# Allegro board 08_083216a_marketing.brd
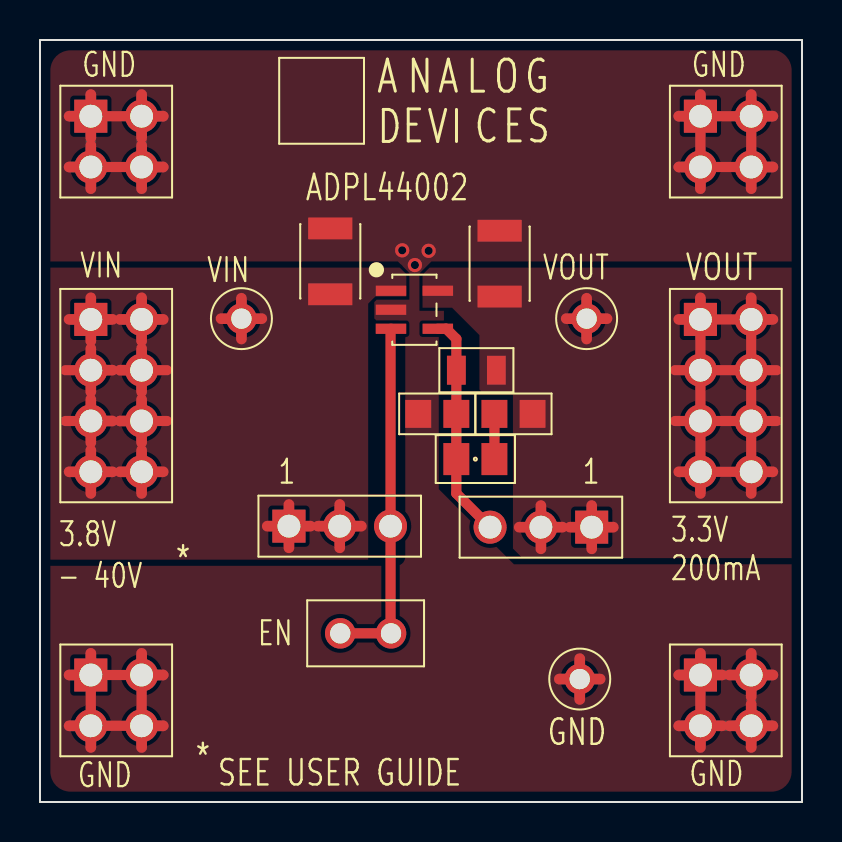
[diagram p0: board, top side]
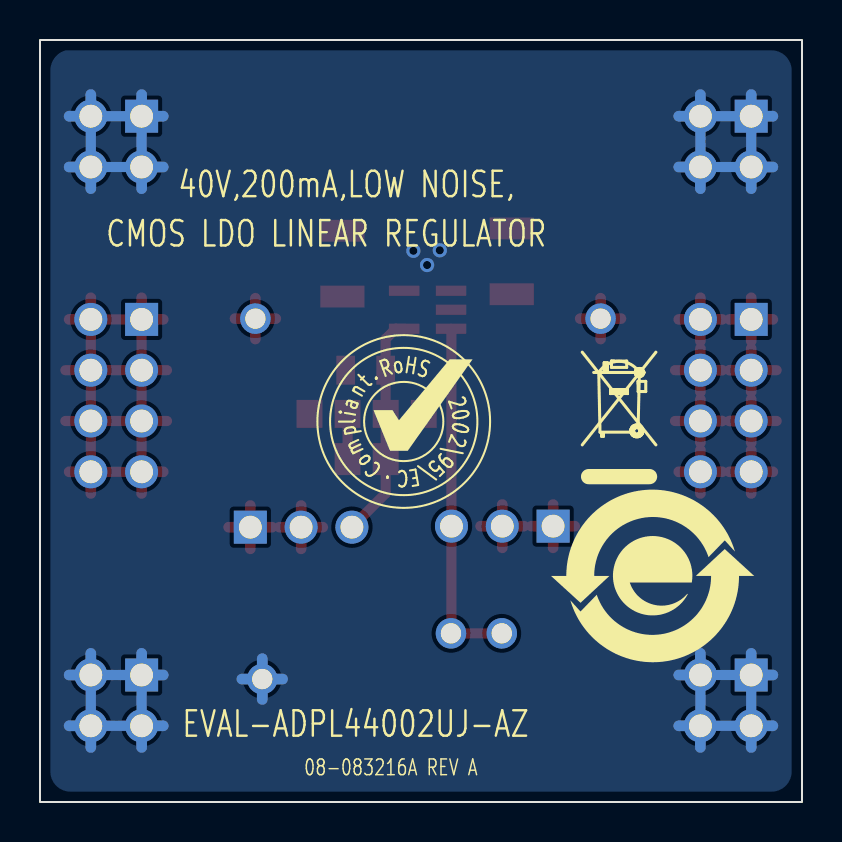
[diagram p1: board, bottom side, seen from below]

Outline 38.1 x 38.1 mm; copper layers: TOP, BOTTOM. Coordinates in mm from the lower left corner of the outline.

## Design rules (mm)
constraint set DEFAULT: min track width 0.152
net group VOUT: nets _N9 _N15 VOUT

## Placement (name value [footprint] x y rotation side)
C1  2.2uF  [C1210H87]  14.51 27.03 270 top
C2  2.2uF  [C1210H87]  22.98 26.92 270 top
C3  TBD0805  [C0805]  21.77 17.14 0 top
J1  PEC04DAAN  [CNTHMHDR2X4L400W200H343]  2.54 24.13 270 top
J2  PEC02SAAN  [CNSULLINSPEC02SAAN]  15.01 8.43 0 top
J3  PEC04DAAN  [CNTHMHDR2X4L400W200H343]  33.02 24.13 270 top
J4  PEC02DAAN  [CNSULLINSXXC02DAAN]  2.54 34.29 270 top
J5  PEC02DAAN  [CNSULLINSXXC02DAAN]  33.02 34.29 270 top
J6  PEC02DAAN  [CNSULLINSXXC02DAAN]  2.54 6.35 270 top
J7  PEC02DAAN  [CNSULLINSXXC02DAAN]  33.02 6.35 270 top
JP1  PEC03SAAN  [CNTHMHDR1X3L300W100H343_A]  12.45 13.79 0 top
JP2  PEC03SAAN  [CNTHMHDR1X3L300W100H343_A]  27.58 13.74 180 top
NOREF  -  []  0 38.1 0 top
NOREF#2  -  []  0 38.1 270 top
NOREF#3  -  []  0 38.1 0 top
NOREF#4  -  []  38.1 0 90 top
NOREF#5  -  []  38.1 0 0 top
NOREF#6  -  []  -234.06 -202.06 0 top
NOREF#7  -  []  0 0 0 top
NOREF#8  -  []  2.54 3.81 0 top
NOREF#9  -  []  -234.98 -203.94 0 top
NOREF#10  -  []  2.54 3.81 0 top
NOREF#11  -  []  38.1 0 90 top
NOREF#12  -  []  18.77 55.04 0 top
NOREF#13  -  []  0 0 0 top
NOREF#14  -  []  0 0 0 top
NOREF#15  -  []  38.1 38.1 180 top
NOREF#16  -  []  -223.27 121.03 0 top
NOREF#17  -  []  68.43 43.66 0 top
NOREF#18  -  []  3.81 3.81 0 top
NOREF#19  -  []  9.35 15.95 180 bottom
NOREF#20  -  []  7.47 11.3 180 bottom
NOREF#21  -  []  19.91 19.02 180 bottom
R1  17.4K  [R0805H20]  21.82 21.59 180 top
R2  10K  [R0805]  19.86 19.41 180 top
R3  TBD0805  [R0805]  23.67 19.41 180 top
TP1  WHT  [CNKEY5001TP]  10.07 24.17 90 top
TP2  WHT  [CNKEY5001TP]  27.33 24.17 90 top
TP3  BLK  [CNKEY5001TP]  26.99 6.15 0 top
U1  ADPL44002AUJZ  [TSOT-5]  18.72 24.61 270 top

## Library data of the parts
C1 C2 = CAP: Tolerance: 10; User Part Number: UPN; alternate symbols: (C1210H87); tolerance: 10
C3 = CAP: User Part Number: UPN; alternate symbols: (C0805)
J1 J3 = CN8P_ODD_EVEN: Tolerance: N/A; User Part Number: UPN; alternate symbols: (CNTHMHDR2X4L400W200H343); tolerance: N/A
J2 = CN2P: Tolerance: N/A; User Part Number: UPN; alternate symbols: (CNSULLINSPEC02SAAN); tolerance: N/A
J4-J7 = CN4P_ODD_EVEN: User Part Number: UPN; Tolerance: N/A; alternate symbols: (CNSULLINSXXC02DAAN); tolerance: N/A
JP1 JP2 = CN3P: User Part Number: UPN; Tolerance: N/A; alternate symbols: (CNTHMHDR1X3L300W100H343_A); tolerance: N/A
R1 = RES: Tolerance: 1; User Part Number: UPN; alternate symbols: (R0805H20); tolerance: 1
R2 = RES: Tolerance: 1; User Part Number: UPN; alternate symbols: (R0805); tolerance: 1
R3 = RES: User Part Number: UPN; alternate symbols: (R0805)
TP1-TP3 = CNTP1P: Tolerance: N/A; User Part Number: UPN; alternate symbols: (CNKEY5001TP); tolerance: N/A
U1 = ADPL44002_V2: User Part Number: UPN; Tolerance: N/A; alternate symbols: (TSOT-5); tolerance: N/A

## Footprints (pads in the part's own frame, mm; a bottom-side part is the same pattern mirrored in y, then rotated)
C0805
  rect 1.295x1.6 smd: 1(-0.953,0) 2(0.953,0)
C1210H87
  rect 1.092x2.21 smd: 1(-1.646,0) 2(1.646,0)
CNKEY5001TP
  round 1.524 hole 1.016: 1(0,0)
CNSULLINSPEC02SAAN
  round 1.524 hole 1.016: 1(0,0) 2(2.54,0)
CNSULLINSXXC02DAAN
  rect 1.651x1.651 hole 1.143: 1(0,0)
  round 1.651 hole 1.143: 2(0,2.54) 3(2.54,0) 4(2.54,2.54)
CNTHMHDR1X3L300W100H343_A
  rect 1.651x1.651 hole 1.143: 1(0,0)
  round 1.651 hole 1.143: 2(2.54,0) 3(5.08,0)
CNTHMHDR2X4L400W200H343
  rect 1.651x1.651 hole 1.143: 1(0,0)
  round 1.651 hole 1.143: 2(0,2.54) 3(2.54,0) 4(2.54,2.54) 5(5.08,0) 6(5.08,2.54) 7(7.62,0) 8(7.62,2.54)
R0805
  rect 1.295x1.397 smd: 1(-0.953,0) 2(0.953,0)
R0805H20
  rect 0.94x1.448 smd: 1(-1.001,0) 2(1.001,0)
TSOT-5
  rect 0.508x1.524 smd: 1(-0.95,-1.171) 2(0,-1.171) 3(0.95,-1.171) 4(0.95,1.171) 5(-0.95,1.171)

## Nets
GND: C1.1 C2.1 J4.1 J4.2 J4.3 J4.4(N4) J5.1 J5.2 J5.3 J5.4(N4) J6.1 J6.2 J6.3 J6.4(N4) J7.1 J7.2 J7.3 J7.4(N4) R2.2(N2) TP3.1(N1) U1.2
VIN: C1.2(N2) J1.1 J1.2 J1.3 J1.4 J1.5 J1.6 J1.7 J1.8(N8) JP1.1 JP1.2 TP1.1(N1) U1.1
_N9: C3.2(N2) R3.2(N2)
_N14: J2.1 J2.2(N2) JP1.3(N3) U1.3
_N15: C3.1 JP2.3(N3) R1.2(N2) R2.1 U1.4
VOUT: C2.2(N2) J3.1 J3.2 J3.3 J3.4 J3.5 J3.6 J3.7 J3.8(N8) JP2.1 JP2.2 R1.1 R3.1 TP2.1(N1) U1.5(VOUT)

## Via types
v1: diameter 0.711, hole 0.406, TOP to BOTTOM, 3 vias

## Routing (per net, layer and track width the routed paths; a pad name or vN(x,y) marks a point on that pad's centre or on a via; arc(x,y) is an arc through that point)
GND: length 156.8
  TOP w0.508: J4.4 J4.3 ; J4.1 J4.2 ; J7.1 J7.3 ; J5.4 J5.3 J5.1 J5.2 J5.4 ; J6.3 J6.1 J6.2 J6.4 J6.3
  TOP w0.533: 34.48,3.81 J7.4 ; J7.4 35.56,4.89 ; J7.4 36.64,3.81 ; J7.4 35.56,2.73 ; 1.46,3.81 J6.3 2.54,2.73 ; 34.48,6.35 J7.2 ; J7.2 35.56,7.43 ; J7.2 36.64,6.35 ; J7.2 35.56,5.27 ; 2.54,7.43 J6.1 1.46,6.35 ; 31.94,31.75 J5.3 33.02,30.67 ; 1.46,31.75 J4.3 ; J4.3 2.54,32.83 ; J4.3 2.54,30.67 ; J7.1 33.02,7.43 ; J7.1 31.94,6.35 ; J7.1 34.1,6.35 ; 35.56,30.67 J5.4 36.64,31.75 ; J4.2 5.08,35.37 ; J4.2 6.16,34.29 ; J4.2 5.08,33.21 ; 2.54,33.21 J4.1 ; J4.1 1.46,34.29 ; J4.1 2.54,35.37 ; 36.64,34.29 J5.2 35.56,35.37 ; J7.3 34.1,3.81 ; J7.3 31.94,3.81 ; J7.3 33.02,2.73 ; 26.99,5.13 TP3.1 ; TP3.1 28.01,6.15 ; TP3.1 26.99,7.17 ; TP3.1 25.97,6.15 ; 33.02,35.37 J5.1 31.94,34.29 ; 6.16,3.81 J6.4 5.08,2.73 ; J4.4 6.16,31.75 ; J4.4 5.08,32.83 ; J4.4 5.08,30.67 ; 5.08,7.43 J6.2 6.16,6.35
  BOTTOM w0.508: J4.2 J4.1 J4.3 J4.4 J4.2 ; J7.3 J7.1 J7.2 J7.4 J7.3 ; J5.4 J5.3 J5.1 J5.2 J5.4 ; J6.3 J6.1 J6.2 J6.4 J6.3
  BOTTOM w0.533: 35.56,30.67 J5.4 36.64,31.75 ; 35.56,35.37 J5.2 36.64,34.29 ; 33.02,2.73 J7.3 31.94,3.81 ; 6.16,31.75 J4.4 5.08,30.67 ; 25.97,6.15 TP3.1 ; TP3.1 28.01,6.15 ; TP3.1 26.99,5.13 ; TP3.1 26.99,7.17 ; 35.56,2.73 J7.4 36.64,3.81 ; 5.08,2.73 J6.4 6.16,3.81 ; 5.08,35.37 J4.2 6.16,34.29 ; 35.56,7.43 J7.2 36.64,6.35 ; 6.16,6.35 J6.2 5.08,7.43 ; 2.54,30.67 J4.3 1.46,31.75 ; 2.54,2.73 J6.3 1.46,3.81 ; 31.94,34.29 J5.1 33.02,35.37 ; 31.94,31.75 J5.3 33.02,30.67 ; 31.94,6.35 J7.1 33.02,7.43 ; 1.46,6.35 J6.1 2.54,7.43 ; 2.54,35.37 J4.1 1.46,34.29
  vias: v1(18.11,27.58) v1(18.75,26.85) v1(19.43,27.56)
VIN: length 48.1
  TOP w0.508: J1.4 6.35,21.59 ; J1.6 6.35,19.05 ; J1.5 1.27,19.05 ; J1.3 1.27,21.59
  TOP w0.533: 2.54,17.97 J1.5 ; J1.5 3.62,19.05 ; J1.5 2.54,20.13 ; J1.7 2.54,17.59 ; J1.7 2.54,15.43 ; J1.7 3.62,16.51 ; J1.7 1.46,16.51 ; 9.05,24.17 TP1.1 ; TP1.1 10.07,23.15 ; TP1.1 10.07,25.19 ; TP1.1 11.09,24.17 ; 12.45,12.71 JP1.1 ; JP1.1 13.53,13.79 ; JP1.1 12.45,14.87 ; JP1.1 11.36,13.79 ; J1.2 5.08,25.21 ; J1.2 4,24.13 ; J1.2 5.08,23.05 ; J1.2 6.16,24.13 ; 2.54,23.05 J1.1 ; J1.1 1.46,24.13 ; J1.1 3.62,24.13 ; J1.1 2.54,25.21 ; 4,21.59 J1.4 ; J1.4 5.08,22.67 ; J1.4 5.08,20.51 ; J1.8 5.08,17.59 ; J1.8 4,16.51 ; J1.8 5.08,15.43 ; J1.8 6.16,16.51 ; JP1.2 14.99,14.87 ; JP1.2 16.07,13.79 ; JP1.2 13.9,13.79 ; JP1.2 14.99,12.71 ; J1.3 3.62,21.59 ; J1.3 2.54,22.67 ; J1.3 2.54,20.51 ; 5.08,17.97 J1.6 ; J1.6 4,19.05 ; J1.6 5.08,20.13
_N9: length 2.3
  TOP w0.508: R3.2 C3.2
_N14: length 17.8
  TOP w0.508: U1.3 17.53,23.64 JP1.3 17.53,8.46 J2.2 J2.1
_N15: length 11.3
  TOP w0.508: U1.4 20.31,23.66 20.82,23.15 R1.2 20.82,19.41 R2.1 C3.1 20.82,15.43 JP2.3
VOUT: length 51.9
  TOP w0.508: J3.6 J3.8 J3.7 J3.5 ; J3.6 J3.5 ; J3.6 J3.4 ; J3.6 36.83,19.05 ; J3.5 31.75,19.05 ; J3.5 J3.3 ; J3.3 31.75,21.59 ; J3.3 J3.4 ; J3.3 J3.1 J3.2 J3.4 ; J3.4 36.83,21.59
  TOP w0.533: JP2.2 25.04,14.82 ; JP2.2 23.96,13.74 ; JP2.2 25.04,12.66 ; JP2.2 26.13,13.74 ; TP2.1 28.35,24.17 ; TP2.1 26.31,24.17 ; TP2.1 27.33,25.19 ; TP2.1 27.33,23.15 ; JP2.1 27.58,14.82 ; JP2.1 28.67,13.74 ; JP2.1 27.58,12.66 ; JP2.1 26.5,13.74 ; 33.02,25.21 J3.1 31.94,24.13 ; 36.64,16.51 J3.8 35.56,15.43 ; 31.94,16.51 J3.7 33.02,15.43 ; 36.64,24.13 J3.2 35.56,25.21

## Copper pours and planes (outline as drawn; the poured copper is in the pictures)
GND on TOP: 0.52,36.58 0.81,37.29 1.52,37.58 36.83,37.58 37.37,37.2 37.58,36.58 37.58,27.03 19.57,27.03 18.97,26.43 18.97,24.56 20.19,24.56 20.19,24.03 19.94,23.77 19.94,15.65 23.7,11.89 37.58,11.89 37.58,1.52 37.29,0.81 36.58,0.52 1.52,0.52 0.81,0.81 0.52,1.52 0.52,11.81 17.83,11.81 18.14,11.95 18.26,12.27 18.26,23.72 17.91,24.08 16.81,24.08 16.71,24.18 16.71,24.99 16.84,25.12 18.21,25.12 18.21,26.3 18.25,26.35 18.26,26.42 18.2,26.69 18.02,26.9 17.9,27.03 0.52,27.03
GND on BOTTOM: 1.52,0.52 0.81,0.81 0.52,1.52 0.52,36.58 0.81,37.29 1.52,37.58 36.83,37.58 37.37,37.2 37.58,36.58 37.58,1.52 37.29,0.81 36.58,0.52
VIN on TOP: 0.52,12.12 0.52,26.72 17.98,26.72 18.31,26.39 18.31,25.27 16.76,25.27 16.41,24.92 16.41,12.12
VOUT on TOP: 23.65,20.35 23.47,20.52 22.07,20.52 21.97,20.62 21.97,23.34 20.6,24.71 19.13,24.71 19.13,26.37 19.48,26.72 37.58,26.72 37.58,12.19 24.13,12.19 23.65,12.67

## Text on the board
Ref Des/Silkscreen Bottom: 08-083216A REV A | EVAL-ADPL44002UJ-AZ | 40V,200mA,LOW NOISE, | CMOS LDO LINEAR REGULATOR
User.Comments: 5.    INSTALL SHUNT (M067636) JP1 - PIN2 AND 3 , JP2 -PIN1 AND 2.
Ref Des/Silkscreen Top: - 40V | 3.8V | GND | VIN | EN | VOUT | 3.3V | 200mA | * | SEE USER GUIDE | ADPL44002 | A | D | E | N | V | I | L | C | O | G | S
DIMENSION: " " | (REF) | DIA MAX
PAGE_OUTLINE: 19JUN24
User.6: J1 | J3 | GND | VIN | EN | JP1 | J2 | U3 | VOUT | R2 | R1 | C3 | C4 | R3 | PN | ADP7142-EVALZ | ADP7142ACPZN-R7 | S5 | JP2 | C1 | C2 | A | D | E | N | V | I | L | C | O | G | S
User.36: FIGURE | SIZE | 16.0 | 40.0 | 45.0 | PLATED | FINISHED HOLES IN MILS | ALL UNITS ARE IN MILS | QTY | 3 | 5 | 8 | 30 | TOLERANCE/NOTES
User.38: FAB NOTES REVISION: NOVEMBER 21 2022 | 8.   IMPEDANCE REQUIREMENTS: IF NO STACKUP IS DEFINED, THE VENDOR IS ALLOWED TO ADJUST THE DIELECTRIC | 13.  PLATING SPECIFICATION: | 1.   DIMENSIONS ARE IN INCHES (EXCEPT WHERE NOTED). | ALL DOCUMENTS & SPECIFICATIONS REFERRED TO BELOW SHOULD BE THE LATEST REVISIONS. | 2.  BOARD MATERIAL:(USE CHECKED ITEMS) | 3.   ALL LAMINATES & BONDING MATERIALS SHOULD BE SELECTED FROM IPC-4101 OR IPC-4103,(TG>170 DEGC TD>300 DEGC) | 4.   REFER TO IPC-6010 SERIES, CLASS 2 FOR FABRICATION. | 5.   REFER TO LAMINATION DIAGRAM FOR OVERALL BOARD THICKNESS, TOLERANCE APPLIES AFTER ALL LAMINATION AND PLATING | 6.   BOW & TWIST NOT TO EXCEED 0.0075 INCHES (0.75%) PER LINEAR INCH AND SHOULD BE MEASURED PER IPC-TM-650, METHOD 2.4.22. | 7.   ACCEPTABILITY PER ADI SPECIFICATION TST00115. | 9.   FILLET OPTIONS TO ENHANCE RELIABILITY AT PAD JUNCTIONS WHERE SPACING PERMITS. | 10.  THIEVING: | 11.  LAYER TO LAYER REGISTRATION SHALL BE WITHIN 0.003 INCHES. | 12.  DRILL SIZES ARE FINISHED HOLE SIZES. ALL HOLES SHALL BE LOCATED WITHIN 0.005 INCHES DTP,UNLESS SPECIFIED. | 14.  SURFACE FINISH: | 15.  SOLDERMASK: | 16.  APPLY SILKSCREEN TO BOTH SIDES USING A NON-CONDUCTIVE, EPOXY BASED INK PER ARTWORK. | (X) WHITE | ( ) OTHER | PROCESSES. FINISHED THICKNESS MEASURED FROM TOP COPPER TO BOTTOM COPPER. | (X)  ISOLA 370HR OR S1000-2 OR IT180 OR EQUIVALENT | ( )  ISOLA-FR408HR OR EQUIVALENT | ( )  ISOLA IS410 | ( )  MEGTRON 6 | ( )  NELCO-4000-13 | ( )  ROGERS 4350B | ( ) ROGERS 3003 | ( ) ARLON 85N | ( ) EM370D | ( )  OTHER ________________________ | ( ) FILLETS ALLOWED | (X) FILLETS NOT ALLOWED | ( ) VENDOR MAY ADD THIEVING TO COMPENSATE FOR LOW COPPER DENSITY AREAS MAINTAINING A MINIMUM | (X) VENDOR MAY NOT ADD THIEVING TO COMPENSATE FOR LOW COPPER DENSITY AREAS. | (X) LPI | ( ) OTHER_________ | COLOR | (X) GREEN | HINDER PROPER SOLDER WICKING. BARREL RELIEF ON SOLDERMASK ALLOWED IN UNFILLED VIA IN PAD HOLES. | (X) REFER TO LAMINATION DIAGRAM FOR FINISHED COPPER WEIGHT/THICKNESS REQUIRMENTS | (X) IMMERSION GOLD (ENIG) 1.58-3.94 MICRO INCHES OVER 118-236 MICRO INCHES MIN. OF ELECTROLESS NICKEL PER IPC-4552 | ( ) OSP (ORGANIC SOLDERABILITY PRESERVATIVE) | ( ) IMMERSION SILVER | ( ) SOFT WIRE BONDABLE GOLD 30-50 MICRO INCHES OF SOFT WIRE | ( ) EDGE CONNECTOR FINGERS ARE TO BE PLATED WITH 100 MICRO-INCHES(.0001") OF LOW STRESS | THICKNESS & TRACE WIDTHS TO MEET THE IMPEDANCE REQUIREMENT. IF SPECIFIED, THE VENDOR MUST | TRACE WIDTH & SPACING THAT IMPACT THE REQUIREMENTS MUST HAVE WRITTEN APPROVAL FROM ADI. | MINIMUM BARREL PLATING OF 0.001 INCHES. PLATED HOLES SHALL NOT BE ROUGH OR IRREGULAR SO AS TO | SOLDERMASK OVER BARE COPPER OR BARE GOLD (BOTH SIDES) TO MEET IPC-SM-840. | IF PRESENT,DO NOT MODIFY SOLDERMASK DEFINED PADS (MASK OPENINGS LESS THAN COPPER PAD) WITHOUT APPROVAL. | MEET THE REQUIREMENTS LISTED IN THE IMPEDANCE TABLE. ANY ADJUSTMENT MADE TO THE DEFINED STACKUP, | UL FLAMMABILITY RATING 94V-0. BOARD MATERIAL & CONSTRUCTION SHALL MEET THE REQUIREMENTS OF UL796/UL796F. | BONDABLE GOLD OVER 100-150 MICRO INCHES OF NICKEL | NICKEL UNDER 30 MICRO-INCHES (.00003') OF GOLD | 0.100 INCH CLEARANCE FROM ALL COPPER FEATURES, | THE STARTING COPPER WEIGHT/THICKNESS CAN VARY AS LONG AS THE FINISHED COPPER | WEIGHT/THICKNESS IS NOT LESS THAN THE SPECIFIED VALUE. | UNLESS OTHERWISE SPECIFIED | HOMOGENOUS MATERIALS IN THIS BOARD SHALL BE COMPLAINT WITH THE EU DIRECTIVE 2002/95/EC | WORKMANSHIP SHALL CONFORM TO IPC-A-600, CLASS 2. | 21.  INTENTIONAL SHORTS: | 17.  FINAL ELECTRICAL TEST TO BE PERFORMED USING PROVIDED IPC-D-356A NETLIST OR ODB++ FORMAT FILE. | 22.  PEMNUTS: | 23.  MANUFACTURER TO ETCH/STAMP WITH PERMANENT NON-CONDUCTIVE INK | ON SECONDARY SIDE UNLESS OTHERWISE SPECIFIED: | 18.  A TIME DOMAIN REFLECTOMETER REPORT (TDR) FOR EACH IMPEDANCE CONTROLLED LAYER & A CERTIFICATE | 19.  IF PRESENT, ALL BLIND/BURIED VIAS WITH AN ASPECT RATIO <1:1 TO BE PLATED SHUT WITH COPPER WHEN | 20.  FOR VIA FILL INFORMATION REFER TO DRILL CHART: | 25. PANELIZATION: | 27.  MINIMUM DESIGN LINE WIDTH IS .011 INCH. | 28.  MINIMUM DESIGN LINE SPACING IS .006 INCH. | IS ACCEPTABLE, ALL OTHER INSTANCES MUST BE REPORTED. | IF AN INTENTIONAL SHORT REPORT IS SUPPLIED AND DOES NOT MATCH THE FAB DATA THEN | THE PCB SHALL HAVE A VERIFICATION STAMP. | ( )  NON-CONDUCTIVE EPOXY FILL ALL 0.XXXX INCHES DRILLED VIAS | ( )  COPPER FILL ALL 0.XXXX INCHES DRILLED VIAS | ( ) PEMNUTS TO BE INSTALLED BY FABRICATOR | ( ) PEMNUTS NOT TO BE INSTALLED BY FABRICATOR | ( ) NOT APPLICABLE | USED AS VIA-IN-PAD OR AS A STACKED VIA. BLIND/BURIED VIAS WITH AN ASPECT RATIO >1:1 TO BE FILLED | A. UL CODE-FLAMMABILITY RATING FOR THOSE APPROVED MATERIALS(IF APPLICABLE) | B. DATE CODE | C. LOT NUMBER | D. MANUFACTURER LOGO | BOARDS TO BE SHIPPED IN ARRAY AND KEPT INTACT | PANEL TO BE SUBJECTED TO CUSTOMERS APPROVAL | PANEL SOLDER PASTE STENCIL GERBER TO BE PROVIDED TO ANALOG | CAN'T BE PERFORMED BECAUSE THE TRACE LENGTH IS TOO SHORT ON THE OUTER LAYERS AT THE PIN ESCAPES | ADI APPROVAL IS REQUIRED. | OF COMPLIANCE SHALL BE PROVIDED BY VENDOR AT TIME OF SHIPMENT. INSTANCES WHERE TDR TESTING | WITH NON-CONDUCTIVE EPOXY. | NOTES: | TOOLING: | FINISH: | MATERIAL: | TESTING: | MISCELLANEOUS:
